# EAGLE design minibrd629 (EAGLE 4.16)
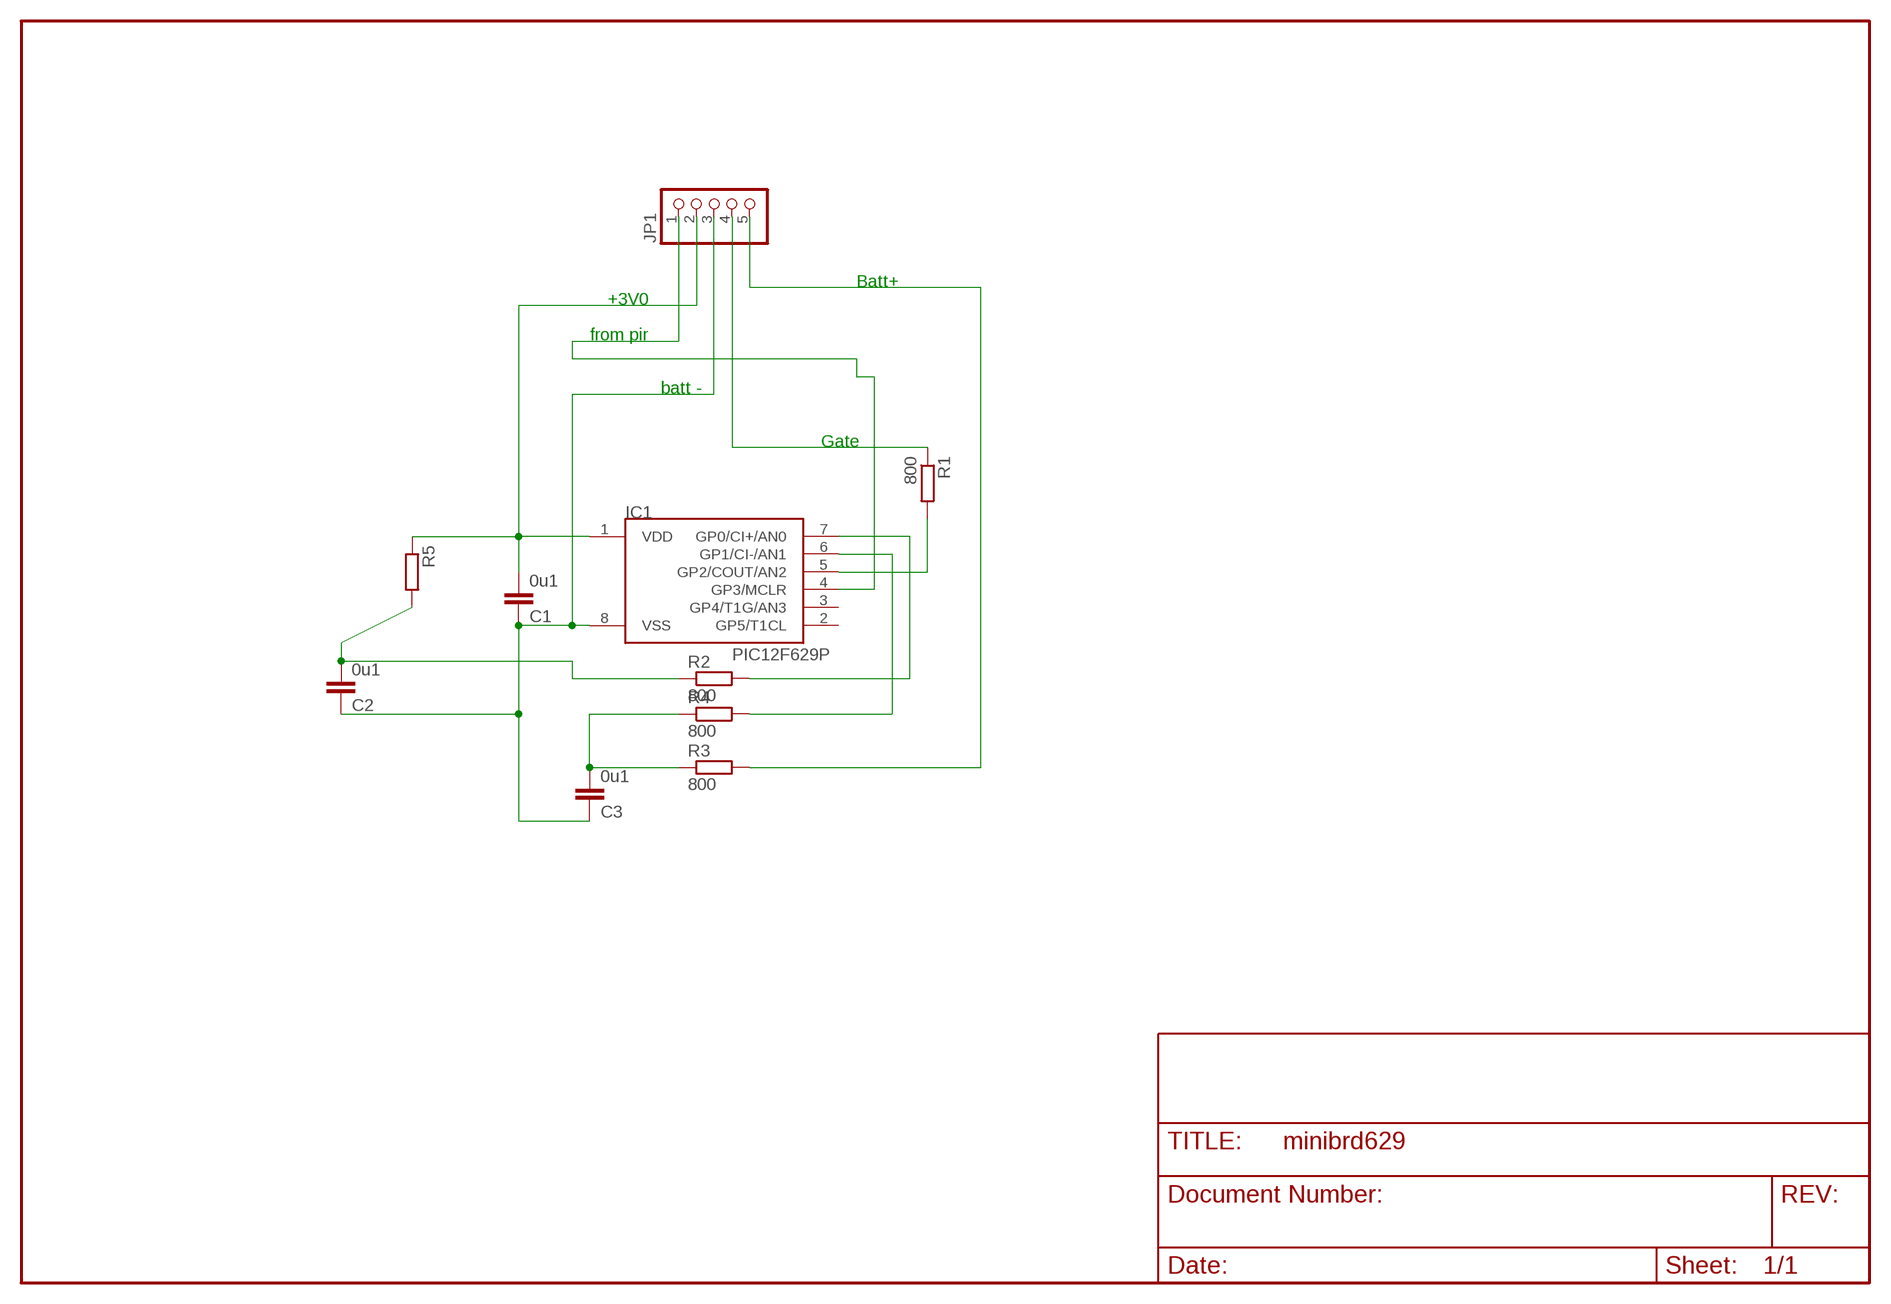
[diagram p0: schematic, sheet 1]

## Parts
C1  0u1  C-EUC1206  [C1206]
C2  0u1  C-EUC1206  [C1206]
C3  0u1  C-EUC1206  [C1206]
IC1  PIC12F629P  [DIL8]
JP1  PINHD-1X5  [1X05]
R1  800  R-EU_R1206  [R1206]
R2  800  R-EU_R1206  [R1206]
R3  800  R-EU_R1206  [R1206]
R4  800  R-EU_R1206  [R1206]
R5  R-EU_0613/5V  [P0613V]

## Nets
GATE: JP1.4 R1.1
N$1: IC1.5(GP2/COUT/AN2) R1.2
N$4: IC1.7(GP0/CI+/AN0) R2.2
N$5: C2.2 R2.1 R5.2
N$7: C3.2 R3.1 R4.1
N$8: IC1.6(GP1/CI-/AN1) R4.2
PIR: IC1.4(GP3/MCLR) JP1.1
V3: C1.2 IC1.1(VDD) JP1.2 R5.1
V+: JP1.5 R3.2
V-: C1.1 C2.1 C3.1 IC1.8(VSS) JP1.3
Unconnected: IC1.2(GP5/T1CL) IC1.3(GP4/T1G/AN3)

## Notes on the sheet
- Batt+
- +3V0
- from pir
- batt -
- Gate

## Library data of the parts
C1-C3 = rcl:C-EU: CAPACITOR, European symbol
IC1 = microchip-3:PIC12F6*: uPC nW 1k Program Flash memory 2x Timer Comparator 10b A/D converter/ 4xIN
JP1 = pinhead:PINHD-1X5: PIN HEADER
R1-R5 = rcl:R-EU_: RESISTOR, European symbol

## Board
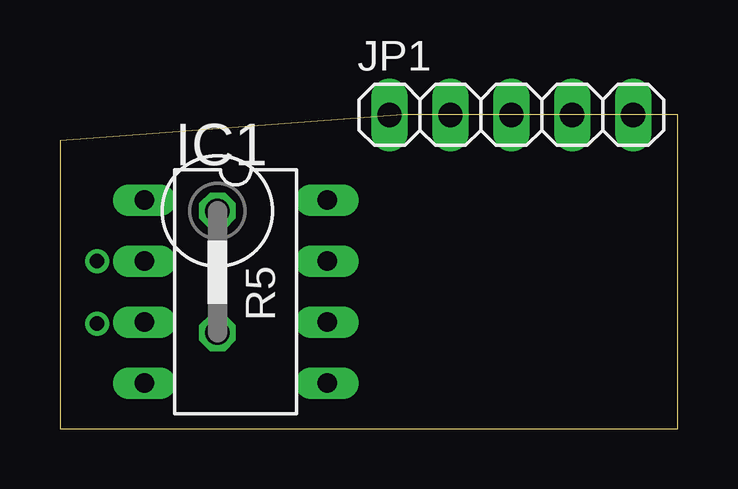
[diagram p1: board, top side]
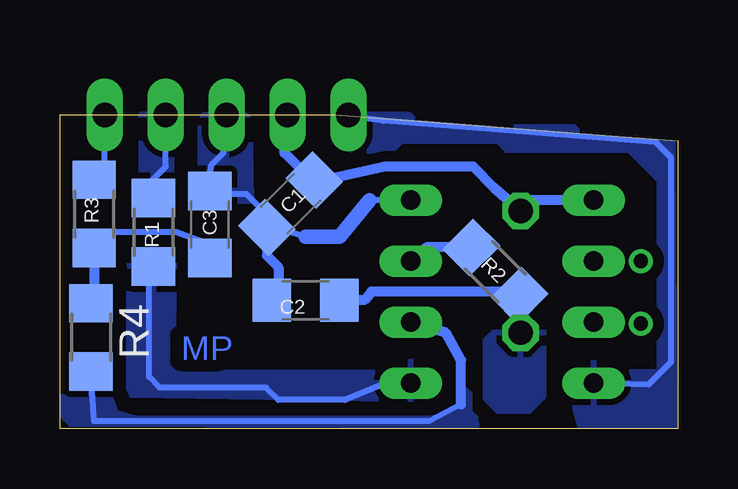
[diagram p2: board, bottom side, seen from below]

Size 25.77 x 13.08 mm. Coordinates in mm from the lower left corner, seen from the top.
Outline: 0,0 25.77,0 25.77,13.07 18,13.07 14.31,13.08 0,11.99 0,0
Copper layers (1*16): Top 0.035mm / dielectric 1.5mm / Bottom 0.035mm
Design rules "default": minimum track width 10mil, minimum drill 24mil, track to track 18mil, track to pad 18mil, pad to pad 8mil, via to via 8mil, smd to smd 8mil, copper to edge 1mil, drill to drill 8mil, minimum pad ring 10mil, minimum via ring 8mil, stop-mask expansion 4mil, vias tented up to drill 0mil, thermal gap 10mil

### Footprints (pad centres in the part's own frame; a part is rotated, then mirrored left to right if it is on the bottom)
C1206 = smd 1.6 x 1.8: 1 -1.4,0; 2 1.4,0
DIL8 = drill 0.813 long: 1 -3.81,-3.81; 2 -1.27,-3.81; 3 1.27,-3.81; 4 3.81,-3.81; 5 3.81,3.81; 6 1.27,3.81; 7 -1.27,3.81; 8 -3.81,3.81
1X05 = drill 1.016 long: 1 -5.08,0; 2 -2.54,0; 3 0,0; 4 2.54,0; 5 5.08,0
R1206 = smd 1.6 x 1.803: 1 -1.422,0; 2 1.422,0
P0613V = drill 1.016 octagon: 1 -2.54,0; 2 2.54,0

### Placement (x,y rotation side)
C1  16.15,9.37 45 bottom
C2  15.53,5.36 0 bottom
C3  19.52,8.5 270 bottom
IC1  7.33,5.71 270 top
JP1  18.82,13.08 0 top
R1  21.87,8.19 270 bottom
R2  7.61,6.55 135 bottom
R3  24.35,8.95 90 bottom
R4  24.47,3.81 270 bottom
R5  6.57,6.54 270 top

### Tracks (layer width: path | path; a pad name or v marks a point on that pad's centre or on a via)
GATE
  Bottom 0.254: JP1.4 21.36,10.92 22.06,10.22 22.06,9.52 21.97,9.61 R1.1
  pour Bottom: 21.11,13.14 22.31,13.14 22.38,13.08 22.38,10.66 22.5,10.54 21.23,10.54 21.11,10.66 21.11,13.01
N$1
  Bottom 0.254: IC1.5 12.34,1.84 13.87,1.2 16.66,1.2 17.17,1.71 21.62,1.71 22.06,2.15 22.06,6.28 21.55,6.79 R1.2
  pour Bottom: 11.46,2.79 10.57,2.85 9.99,2.79 9.99,1.2 10.5,1.2 22.76,1.39 22.89,1.65 22.89,7.42 22.76,7.55 21.04,7.55 20.98,7.49 21.04,4.38 20.47,3.11 19.71,2.34 12.66,2.34 12.47,2.54 11.71,2.54
N$2  (via drill 0.6)
  other vias: 1.55,4.38
N$3  (via drill 0.6)
  other vias: 1.55,6.98
N$4
  Bottom 0.406: IC1.7 11.14,6.92 10.5,7.55 R2.2
N$5
  Bottom 0.406: C2.2 13.08,5.36 12.79,5.71 6.88,5.71 6.76,5.52 6.74,5.54 R2.1 6.6,4.28 6.69,4.19 6.57,4.06 R5.2
  pour Bottom (isolate 0.61): 5.74,4.57 7.14,4.57 8.03,3.68 8.03,1.27 7.26,0.5 6.44,0.5 5.61,1.33 5.61,4.38 5.74,4.5
N$7
  Bottom 0.254: C3.2 19.39,7.62 20.92,8.19 23.96,8.19 24.47,7.55 24.45,7.53 R3.1 | R4.1 24.47,5.2 24.41,5.14 24.35,5.2
  Bottom 0.406: R3.1 24.35,5.2
N$8
  Bottom 0.254: R4.2 24.47,2.15 24.35,0.31 10.38,0.31 9.04,1.01
  Bottom 0.406: 9.04,1.01 9.04,2.85 9.68,4 IC1.6
  pour Bottom (rank 2): 8.41,1.2 8.47,0.38 8.41,0.12 25.3,0.19 25.62,0.5 25.62,1.58 25.3,1.9 23.9,1.9 23.71,1.39 23.46,0.69 22.63,0.44 10.25,0.44 8.85,0.82 8.98,1.71
PIR
  Bottom 0.254: IC1.4 1.23,1.84 0.28,2.79 0.28,11.3 0.91,11.93 12.28,12.82 13.74,13.01 JP1.1
  pour Bottom (rank 2): 1.99,2.73 3.77,2.73 4.34,2.15 4.34,1.01 4.09,0.12 0.15,0.12 0.22,11.87 0.34,12 3.77,12 4.34,12.57 10.69,12.57 11.2,13.08 13.74,13.08 14.31,12.5 14.31,12.38 13.23,11.3 12.22,11.3 11.52,12 7.52,12 7.14,11.62 2.06,11.62 0.79,10.35 0.79,2.41 0.72,2.34 1.99,2.34 2.18,2.54
V3
  Bottom 0.406: IC1.1 6.19,9.52 6.57,9.14 R5.1 7.65,10.03 8.53,10.92 12.22,10.92 14.76,10.35 14.77,10.36 C1.2 15.28,10.36 16.41,11.49 16.41,13.14 16.35,13.2 16.28,13.14 JP1.2
V+
  Bottom 0.254: R3.2 24.37,10.37 24.47,10.47 23.9,11.04 JP1.5
V-
  Bottom 0.254: C3.1 19.46,10.98 18.95,11.49 18.95,13.01 18.89,13.08 JP1.3 | C3.1 18.76,9.59 | IC1.8 12.85,9.52 | 15.52,8 16.79,8.38 C1.1 17.14,8.92 18,9.77 19.08,9.77 19.14,9.71 19.33,9.9 C3.1
  Bottom 0.406: C1.1 17.14,7.21 16.66,6.73 16.66,5.46 16.85,5.27 16.93,5.34 C2.1
  Bottom 0.61: 12.85,9.52 14.12,8 15.52,8
  pour Bottom: 20.03,9.52 19.9,9.9 19.9,12.57 19.77,13.08 18.06,13.08 17.87,12.82 17.81,9.46

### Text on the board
Bottom: MP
